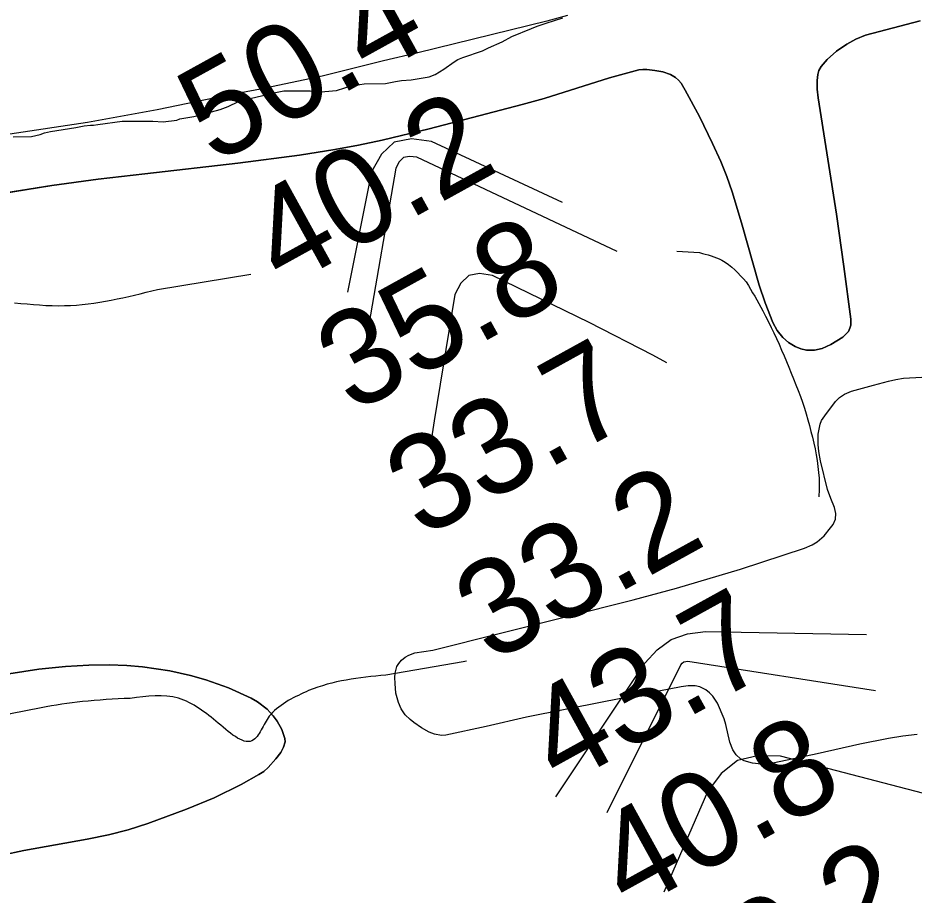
# Model space of a CAD drawing. Extents: x 3177385 to 3215275, y 903885 to 929304.
# Drawn here: x 3183124 to 3183752, y 912004 to 912619 of the extents above; entities that cross this region are included whole.
import ezdxf

# ---------------------------------------------------------------- set-up
doc = ezdxf.new("R2010")
doc.units = 0
for name, color, linetype in [('V-BORW-LINE', 7, 'Continuous'), ('V-LEVE-TOET', 7, 'Continuous'), ('V-RIVR-RANG', 7, 'Continuous'), ('V-SITE-VEGE', 7, 'Continuous'), ('V-TOPO-MAJR', 7, 'Continuous'), ('V-TOPO-MINR', 7, 'Continuous'), ('V-TOPO-SHOR', 7, 'Continuous')]:
    doc.layers.add(name, color=color, linetype=linetype)

msp = doc.modelspace()

# ---------------------------------------------------------------- linework, layer by layer
at = {"layer": 'V-BORW-LINE'}
for p, q in [((3183586.04, 912455.63), (3183601.93, 912454.61)), ((3183221.95, 912428.87), (3183287.23, 912439.53)), ((3183685.66, 912283.64), (3183685.63, 912283.34)), ((3183436.11, 912167.66), (3183381.87, 912158.44)), ((3183437.37, 912167.9), (3183436.11, 912167.66)), ((3183438.63, 912168.13), (3183437.37, 912167.9))]:
    msp.add_line(p, q, dxfattribs=at)
for points in [[(3183601.93, 912454.61), (3183617.54, 912449.38), (3183634.75, 912434.05)], [(3183121.64, 912419.46), (3183156.79, 912417.46), (3183221.95, 912428.87)], [(3183634.75, 912434.05), (3183646.27, 912413.91), (3183674.24, 912349.76)], [(3183674.24, 912349.76), (3183685.68, 912283.94), (3183685.66, 912283.64)], [(3183381.87, 912158.44), (3183327.82, 912147.49), (3183313.6, 912140.53)], [(3183202.81, 912142.08), (3183169.19, 912139.8), (3183111.68, 912129.65)], [(3183264.53, 912124.8), (3183236.55, 912142.13), (3183202.81, 912142.08)], [(3183313.6, 912140.53), (3183301.13, 912130.64), (3183295.26, 912121.14)], [(3183295.26, 912121.14), (3183289.28, 912112.95), (3183264.53, 912124.8)]]:
    msp.add_spline(points, degree=3, dxfattribs=at)
at = {"layer": 'V-LEVE-TOET'}
msp.add_lwpolyline([(3183509.25, 912620.8), (3183494.82, 912616.84), (3183404.5, 912594.68), (3183380.4, 912589.03), (3183337.43, 912578.35), (3183294.1, 912569.22), (3183270.33, 912564.89), (3183221.7, 912554.72), (3183172.8, 912545.91), (3183118.43, 912537.79)], dxfattribs=at)
at = {"layer": 'V-SITE-VEGE'}
for p, q in [((3183494.33, 912615.54), (3183506.11, 912619.22)), ((3183756.54, 912617.25), (3183718.35, 912607.11)), ((3183470.27, 912606.13), (3183484.09, 912611.87)), ((3183484.09, 912611.87), (3183488.19, 912613.44)), ((3183488.19, 912613.44), (3183494.33, 912615.54)), ((3183463.62, 912602.49), (3183470.27, 912606.13)), ((3183718.35, 912607.11), (3183711.59, 912604.41)), ((3183449.8, 912596.23), (3183453.9, 912598.31)), ((3183453.9, 912598.31), (3183463.62, 912602.49)), ((3183705.17, 912600.8), (3183697.99, 912595.9)), ((3183711.59, 912604.41), (3183705.17, 912600.8)), ((3183435.98, 912591.51), (3183449.8, 912596.23)), ((3183697.99, 912595.9), (3183691.39, 912590.03)), ((3183422.68, 912583.21), (3183429.84, 912588.39)), ((3183429.84, 912588.39), (3183432.39, 912589.95)), ((3183432.39, 912589.95), (3183435.98, 912591.51)), ((3183691.39, 912590.03), (3183687.19, 912585.14)), ((3183412.45, 912578), (3183416.55, 912579.57)), ((3183416.55, 912579.57), (3183422.68, 912583.21)), ((3183559.37, 912582.73), (3183538.87, 912577.1)), ((3183562.11, 912583.12), (3183559.37, 912582.73)), ((3183564.91, 912583.07), (3183562.11, 912583.12)), ((3183570.52, 912582.33), (3183564.91, 912583.07)), ((3183576.18, 912581.37), (3183570.52, 912582.33)), ((3183581.63, 912579.59), (3183576.18, 912581.37)), ((3183585.05, 912577.5), (3183581.63, 912579.59)), ((3183684.77, 912579.47), (3183684.3, 912575.42)), ((3183685.68, 912582.43), (3183684.77, 912579.47)), ((3183687.19, 912585.14), (3183685.68, 912582.43)), ((3183366.8, 912573.06), (3183381.68, 912573.16)), ((3183381.68, 912573.16), (3183388.86, 912574.75)), ((3183388.86, 912574.75), (3183392.96, 912575.3)), ((3183392.96, 912575.3), (3183399.63, 912575.86)), ((3183399.63, 912575.86), (3183412.45, 912578)), ((3183538.87, 912577.1), (3183493.05, 912562.69)), ((3183587.21, 912575.52), (3183585.05, 912577.5)), ((3183588.95, 912573.36), (3183587.21, 912575.52)), ((3183591.81, 912568.62), (3183588.95, 912573.36)), ((3183684.3, 912575.42), (3183684.35, 912569.3)), ((3183286.78, 912562.74), (3183304.72, 912566.98)), ((3183304.72, 912566.98), (3183310.36, 912568.04)), ((3183310.36, 912568.04), (3183328.84, 912568.17)), ((3183328.84, 912568.17), (3183335.52, 912567.19)), ((3183335.52, 912567.19), (3183339.11, 912567.73)), ((3183339.11, 912567.73), (3183347.32, 912568.3)), ((3183347.32, 912568.3), (3183359.1, 912571.98)), ((3183359.1, 912571.98), (3183363.72, 912572.53)), ((3183363.72, 912572.53), (3183366.8, 912573.06)), ((3183601.85, 912550.02), (3183591.81, 912568.62)), ((3183684.35, 912569.3), (3183685.04, 912563.22)), ((3183271.42, 912556.99), (3183278.58, 912560.63)), ((3183278.58, 912560.63), (3183284.73, 912562.73)), ((3183284.73, 912562.73), (3183286.78, 912562.74)), ((3183493.05, 912562.69), (3183477.65, 912558.42)), ((3183685.04, 912563.22), (3183697.88, 912481.59)), ((3183259.64, 912553.31), (3183265.79, 912554.89)), ((3183265.79, 912554.89), (3183271.42, 912556.99)), ((3183477.65, 912558.42), (3183412.28, 912541.4)), ((3183235.55, 912547.49), (3183237.59, 912548.54)), ((3183237.59, 912548.54), (3183247.34, 912550.14)), ((3183247.34, 912550.14), (3183252.46, 912551.21)), ((3183252.46, 912551.21), (3183259.64, 912553.31)), ((3183611.14, 912531.23), (3183601.85, 912550.02)), ((3183146.79, 912539.68), (3183164.74, 912542.38)), ((3183164.74, 912542.38), (3183170.38, 912543.44)), ((3183170.38, 912543.44), (3183175, 912543.99)), ((3183175, 912543.99), (3183177.05, 912544)), ((3183177.05, 912544), (3183180.12, 912544.54)), ((3183180.12, 912544.54), (3183197.05, 912546.71)), ((3183197.05, 912546.71), (3183218.61, 912546.86)), ((3183218.61, 912546.86), (3183225.8, 912546.4)), ((3183225.8, 912546.4), (3183235.55, 912547.49)), ((3183120.63, 912535.91), (3183133.47, 912536)), ((3183133.47, 912536), (3183139.62, 912537.58)), ((3183139.62, 912537.58), (3183142.69, 912538.63)), ((3183142.69, 912538.63), (3183146.79, 912539.68)), ((3183412.28, 912541.4), (3183379.42, 912533.52)), ((3183362.89, 912530.02), (3183346.28, 912526.91)), ((3183379.42, 912533.52), (3183362.89, 912530.02)), ((3183616.85, 912518.46), (3183611.14, 912531.23)), ((3183321.56, 912522.96), (3183278.16, 912517.27)), ((3183346.28, 912526.91), (3183321.56, 912522.96)), ((3183278.16, 912517.27), (3183212.9, 912509.98)), ((3183621.04, 912507.92), (3183616.85, 912518.46)), ((3183180.31, 912506.12), (3183147.79, 912501.62)), ((3183212.9, 912509.98), (3183180.31, 912506.12)), ((3183624.78, 912497.23), (3183621.04, 912507.92)), ((3183147.79, 912501.62), (3183101.6, 912494.25)), ((3183631.35, 912475.55), (3183624.78, 912497.23)), ((3183697.88, 912481.59), (3183703.21, 912444.83)), ((3183643.8, 912431.84), (3183631.35, 912475.55)), ((3183703.21, 912444.83), (3183708.12, 912408.05)), ((3183647.93, 912419.5), (3183643.8, 912431.84)), ((3183653.33, 912405.6), (3183647.93, 912419.5)), ((3183656.29, 912400.1), (3183653.33, 912405.6)), ((3183708, 912403.71), (3183707.36, 912401.56)), ((3183708.12, 912408.05), (3183708, 912403.71)), ((3183660.25, 912395.13), (3183656.29, 912400.1)), ((3183704.83, 912397.58), (3183702.37, 912395.47)), ((3183706.27, 912399.44), (3183704.83, 912397.58)), ((3183707.36, 912401.56), (3183706.27, 912399.44)), ((3183664.29, 912391.62), (3183660.25, 912395.13)), ((3183668.9, 912388.82), (3183664.29, 912391.62)), ((3183702.37, 912395.47), (3183693.91, 912390.25)), ((3183672.93, 912387.1), (3183668.9, 912388.82)), ((3183677.05, 912386.17), (3183672.93, 912387.1)), ((3183682.47, 912386.2), (3183677.05, 912386.17)), ((3183687.87, 912387.52), (3183682.47, 912386.2)), ((3183693.91, 912390.25), (3183687.87, 912387.52)), ((3183734.32, 912364.52), (3183739.56, 912365.76)), ((3183739.56, 912365.76), (3183744.89, 912366.57)), ((3183744.89, 912366.57), (3183757.87, 912367.22)), ((3183708.53, 912357.39), (3183716.16, 912359.7)), ((3183716.16, 912359.7), (3183723.9, 912361.65)), ((3183723.9, 912361.65), (3183734.32, 912364.52)), ((3183700.18, 912353.05), (3183703.55, 912355.29)), ((3183703.55, 912355.29), (3183708.53, 912357.39)), ((3183689.71, 912340.31), (3183697.37, 912350.16)), ((3183697.37, 912350.16), (3183700.18, 912353.05)), ((3183685.21, 912327.39), (3183686.49, 912334.46)), ((3183686.49, 912334.46), (3183687.49, 912336.92)), ((3183687.49, 912336.92), (3183689.71, 912340.31)), ((3183685.14, 912320.1), (3183685.21, 912327.39)), ((3183685.63, 912315.18), (3183685.14, 912320.1)), ((3183686.76, 912308.58), (3183685.63, 912315.18)), ((3183691.59, 912288.62), (3183686.76, 912308.58)), ((3183693.91, 912282.23), (3183691.59, 912288.62)), ((3183696.59, 912275.86), (3183693.91, 912282.23)), ((3183697.61, 912271.61), (3183696.59, 912275.86)), ((3183697.25, 912267.82), (3183697.61, 912271.61)), ((3183695.55, 912264.05), (3183697.25, 912267.82)), ((3183689.23, 912256.13), (3183693.85, 912261.55)), ((3183693.85, 912261.55), (3183695.55, 912264.05)), ((3183684.34, 912251.89), (3183689.23, 912256.13)), ((3183630.77, 912232.68), (3183675.63, 912247.4)), ((3183675.63, 912247.4), (3183680.81, 912249.67)), ((3183680.81, 912249.67), (3183684.34, 912251.89)), ((3183585.71, 912219.34), (3183630.77, 912232.68)), ((3183555.44, 912211.19), (3183585.71, 912219.34)), ((3183415.02, 912175.95), (3183555.44, 912211.19)), ((3183392.93, 912168.78), (3183395.63, 912171.02)), ((3183395.63, 912171.02), (3183398.01, 912172.42)), ((3183398.01, 912172.42), (3183402.21, 912173.92)), ((3183402.21, 912173.92), (3183415.02, 912175.95)), ((3183157.33, 912164.51), (3183173.63, 912165.43)), ((3183173.63, 912165.43), (3183187.93, 912165.54)), ((3183187.93, 912165.54), (3183200.46, 912165.06)), ((3183200.46, 912165.06), (3183211.42, 912164.15)), ((3183389.74, 912164.36), (3183391.04, 912166.6)), ((3183391.04, 912166.6), (3183392.93, 912168.78)), ((3183117.75, 912159.36), (3183138.79, 912162.56)), ((3183138.79, 912162.56), (3183157.33, 912164.51)), ((3183211.42, 912164.15), (3183230.6, 912161.35)), ((3183230.6, 912161.35), (3183244.95, 912158.17)), ((3183388.29, 912156.63), (3183388.47, 912159.75)), ((3183388.47, 912159.75), (3183389.74, 912164.36)), ((3183244.95, 912158.17), (3183255.68, 912155.12)), ((3183255.68, 912155.12), (3183271.71, 912149.41)), ((3183388.42, 912152.5), (3183388.29, 912156.63)), ((3183389.07, 912145.82), (3183388.42, 912152.5)), ((3183271.71, 912149.41), (3183287.65, 912142.24)), ((3183390.81, 912139.13), (3183389.07, 912145.82)), ((3183589.17, 912150.25), (3183534.83, 912139.76)), ((3183594, 912150.92), (3183589.17, 912150.25)), ((3183598.88, 912150.82), (3183594, 912150.92)), ((3183602.12, 912150.08), (3183598.88, 912150.82)), ((3183606.39, 912147.98), (3183602.12, 912150.08)), ((3183609.03, 912145.92), (3183606.39, 912147.98)), ((3183611.2, 912143.68), (3183609.03, 912145.92)), ((3183287.65, 912142.24), (3183292, 912139.75)), ((3183292, 912139.75), (3183298.78, 912134.45)), ((3183534.83, 912139.76), (3183480.51, 912128.78)), ((3183614.46, 912138.73), (3183611.2, 912143.68)), ((3183298.78, 912134.45), (3183303.06, 912129.83)), ((3183392.85, 912134.69), (3183390.81, 912139.13)), ((3183395.63, 912130.57), (3183392.85, 912134.69)), ((3183619.12, 912127.84), (3183614.46, 912138.73)), ((3183303.06, 912129.83), (3183305.77, 912126.09)), ((3183398.97, 912127.24), (3183395.63, 912130.57)), ((3183401.68, 912125.2), (3183398.97, 912127.24)), ((3183480.51, 912128.78), (3183452.24, 912122.38)), ((3183620.48, 912123.81), (3183619.12, 912127.84)), ((3183305.77, 912126.09), (3183308.99, 912120.17)), ((3183407.05, 912121.53), (3183401.68, 912125.2)), ((3183412.47, 912118.38), (3183407.05, 912121.53)), ((3183452.24, 912122.38), (3183424.04, 912116.27)), ((3183623.09, 912111.4), (3183620.48, 912123.81)), ((3183308.99, 912120.17), (3183311.1, 912114.05)), ((3183416.14, 912116.89), (3183412.47, 912118.38)), ((3183421.13, 912116.03), (3183416.14, 912116.89)), ((3183424.04, 912116.27), (3183421.13, 912116.03)), ((3183744.5, 912115.59), (3183734.4, 912113.99)), ((3183754.61, 912116.84), (3183744.5, 912115.59)), ((3183311.29, 912111.59), (3183310.34, 912107.75)), ((3183311.1, 912114.05), (3183311.29, 912111.59)), ((3183625.17, 912106.05), (3183623.09, 912111.4)), ((3183714.29, 912110.05), (3183684.33, 912103.23)), ((3183734.4, 912113.99), (3183714.29, 912110.05)), ((3183308.31, 912104.15), (3183304.89, 912099.61)), ((3183310.34, 912107.75), (3183308.31, 912104.15)), ((3183627.53, 912102.47), (3183625.17, 912106.05)), ((3183630.64, 912099.64), (3183627.53, 912102.47)), ((3183684.33, 912103.23), (3183654.39, 912096.86)), ((3183304.89, 912099.61), (3183299.44, 912093.52)), ((3183633.19, 912098.3), (3183630.64, 912099.64)), ((3183639.13, 912096.61), (3183633.19, 912098.3)), ((3183645.14, 912096.03), (3183639.13, 912096.61)), ((3183649.13, 912096.16), (3183645.14, 912096.03)), ((3183654.39, 912096.86), (3183649.13, 912096.16)), ((3183296.38, 912090.89), (3183292.96, 912088.59)), ((3183299.44, 912093.52), (3183296.38, 912090.89)), ((3183292.96, 912088.59), (3183280.52, 912081.61)), ((3183280.52, 912081.61), (3183261.64, 912072.33)), ((3183261.64, 912072.33), (3183242.15, 912064.33)), ((3183242.15, 912064.33), (3183215.07, 912054.34)), ((3183215.07, 912054.34), (3183201.39, 912049.91)), ((3183187.48, 912046.27), (3183172.67, 912043.28)), ((3183201.39, 912049.91), (3183187.48, 912046.27)), ((3183172.67, 912043.28), (3183128.13, 912035.49)), ((3183128.13, 912035.49), (3183113.04, 912032.22))]:
    msp.add_line(p, q, dxfattribs=at)
at = {"layer": 'V-TOPO-MAJR'}
for points in [[(3183579.06, 912377.39), (3183569.2, 912382.79), (3183524.65, 912405.63), (3183456.69, 912438.7), (3183447.76, 912439.92), (3183440.19, 912438.51), (3183434.65, 912433.15), (3183430.47, 912425.17), (3183415.76, 912336.66), (3183413.99, 912324.49)], [(3183501.29, 912073.13), (3183563.7, 912166.78), (3183572.31, 912176.13), (3183582.06, 912183.3), (3183593.52, 912187.22), (3183606.11, 912188.97), (3183719.1, 912186.84)]]:
    msp.add_lwpolyline(points, dxfattribs=at)
at = {"layer": 'V-TOPO-MINR'}
for points in [[(3183505.82, 912489.82), (3183413.99, 912532.59), (3183399.88, 912534.41), (3183387.83, 912532.15), (3183378.89, 912523.78), (3183372.02, 912511.32), (3183355.18, 912426.83)], [(3183544.29, 912455.41), (3183403.65, 912521.47), (3183398.68, 912522.1), (3183394.47, 912521.28), (3183391.38, 912518.29), (3183389.05, 912513.86), (3183369.19, 912398.95)], [(3183537.28, 912062.14), (3183588.83, 912165.56), (3183589.78, 912166.77), (3183590.9, 912167.66), (3183593.82, 912168.13), (3183725.36, 912147.56)], [(3183803.13, 912063.84), (3183658.65, 912101.48), (3183642.65, 912101.87), (3183628.49, 912098.49), (3183617.08, 912089.43), (3183607.51, 912076.61), (3183576.9, 912006.27)]]:
    msp.add_lwpolyline(points, dxfattribs=at)
at = {"layer": 'V-TOPO-SHOR'}
for points in [[(3183493.05, 912562.69), (3183538.87, 912577.1), (3183559.37, 912582.73), (3183562.11, 912583.12), (3183564.91, 912583.07), (3183570.52, 912582.33), (3183576.18, 912581.37), (3183581.63, 912579.59), (3183585.05, 912577.5), (3183587.21, 912575.52), (3183588.95, 912573.36), (3183591.81, 912568.62), (3183601.85, 912550.02), (3183611.14, 912531.23), (3183616.85, 912518.46), (3183621.04, 912507.92), (3183624.78, 912497.23), (3183631.35, 912475.55), (3183643.8, 912431.84), (3183647.93, 912419.5), (3183653.33, 912405.6), (3183656.29, 912400.1), (3183660.25, 912395.13), (3183664.29, 912391.61), (3183668.9, 912388.82), (3183672.93, 912387.1), (3183677.05, 912386.17), (3183682.47, 912386.2), (3183687.87, 912387.52), (3183693.91, 912390.25), (3183702.37, 912395.47), (3183704.83, 912397.58), (3183706.27, 912399.44), (3183707.36, 912401.56), (3183708, 912403.71), (3183708.12, 912408.05), (3183703.21, 912444.83), (3183697.88, 912481.59), (3183685.04, 912563.22), (3183684.35, 912569.3), (3183684.3, 912575.42), (3183684.77, 912579.47), (3183685.68, 912582.43), (3183687.19, 912585.14), (3183691.39, 912590.03), (3183697.99, 912595.9), (3183705.17, 912600.8), (3183711.59, 912604.41), (3183718.35, 912607.11), (3183756.54, 912617.25)], [(3183101.6, 912494.25), (3183147.79, 912501.62), (3183180.31, 912506.12), (3183212.9, 912509.98), (3183278.16, 912517.27), (3183321.56, 912522.96), (3183346.28, 912526.91), (3183362.89, 912530.02), (3183379.42, 912533.52), (3183412.28, 912541.4), (3183477.65, 912558.42), (3183493.05, 912562.69)], [(3183754.61, 912116.84), (3183744.5, 912115.59), (3183734.4, 912113.99), (3183714.29, 912110.05), (3183684.33, 912103.23), (3183654.39, 912096.86), (3183649.13, 912096.16), (3183645.14, 912096.03), (3183639.13, 912096.61), (3183633.19, 912098.3), (3183630.64, 912099.64), (3183627.53, 912102.47), (3183625.17, 912106.05), (3183623.09, 912111.4), (3183620.48, 912123.81), (3183619.12, 912127.84), (3183614.46, 912138.73), (3183611.2, 912143.68), (3183609.03, 912145.92), (3183606.39, 912147.98), (3183602.12, 912150.08), (3183598.88, 912150.82), (3183594, 912150.92), (3183589.17, 912150.25), (3183534.83, 912139.76), (3183480.51, 912128.78), (3183452.24, 912122.38), (3183424.04, 912116.27), (3183421.13, 912116.03), (3183416.14, 912116.89), (3183412.47, 912118.38), (3183407.05, 912121.53), (3183401.68, 912125.2), (3183398.97, 912127.24), (3183395.63, 912130.57), (3183392.85, 912134.69), (3183390.81, 912139.13), (3183389.07, 912145.82), (3183388.42, 912152.5), (3183388.29, 912156.63), (3183388.47, 912159.75), (3183389.74, 912164.36), (3183391.04, 912166.6), (3183392.93, 912168.78), (3183395.63, 912171.02), (3183398.01, 912172.42), (3183402.21, 912173.92), (3183415.02, 912175.95), (3183555.44, 912211.19), (3183585.71, 912219.34), (3183630.77, 912232.68), (3183675.63, 912247.4), (3183680.81, 912249.67), (3183684.34, 912251.89), (3183689.23, 912256.13), (3183693.85, 912261.55), (3183695.55, 912264.05), (3183697.25, 912267.82), (3183697.61, 912271.61), (3183696.59, 912275.86), (3183693.91, 912282.23), (3183691.59, 912288.62), (3183686.76, 912308.58), (3183685.63, 912315.18), (3183685.14, 912320.11), (3183685.21, 912327.39), (3183686.49, 912334.46), (3183687.49, 912336.92), (3183689.71, 912340.31), (3183697.37, 912350.16), (3183700.18, 912353.05), (3183703.55, 912355.29), (3183708.53, 912357.39), (3183716.16, 912359.7), (3183723.9, 912361.65), (3183734.32, 912364.52), (3183739.56, 912365.76), (3183744.89, 912366.57), (3183757.87, 912367.22)], [(3183113.04, 912032.22), (3183128.13, 912035.49), (3183172.67, 912043.28), (3183187.48, 912046.27), (3183201.39, 912049.91), (3183215.07, 912054.34), (3183242.15, 912064.33), (3183261.64, 912072.33), (3183280.52, 912081.61), (3183292.96, 912088.59), (3183296.38, 912090.89), (3183299.44, 912093.52), (3183304.89, 912099.61), (3183308.31, 912104.15), (3183310.34, 912107.75), (3183311.29, 912111.59), (3183311.1, 912114.04), (3183308.99, 912120.17), (3183305.77, 912126.09), (3183303.06, 912129.83), (3183298.78, 912134.45), (3183292.01, 912139.75), (3183287.65, 912142.24), (3183271.71, 912149.41), (3183255.68, 912155.12), (3183244.95, 912158.17), (3183230.6, 912161.35), (3183211.42, 912164.15), (3183200.46, 912165.06), (3183187.93, 912165.54), (3183173.63, 912165.43), (3183157.33, 912164.51), (3183138.79, 912162.56), (3183117.75, 912159.36)]]:
    msp.add_lwpolyline(points, dxfattribs=at)

# ---------------------------------------------------------------- texts
at = {"layer": 'V-RIVR-RANG'}
for s, p in [('50.4', (3183261.67, 912516.12)), ('40.2', (3183310.2, 912428.69)), ('35.8', (3183358.73, 912341.25)), ('33.7', (3183407.26, 912253.82)), ('33.2', (3183455.79, 912166.39)), ('43.7', (3183504.33, 912078.95)), ('40.8', (3183552.86, 911991.52)), ('36.2', (3183601.39, 911904.09))]:
    msp.add_text(s, height=67, rotation=28.88833, dxfattribs=at).set_placement(p)

doc.saveas('drawing.dxf')
